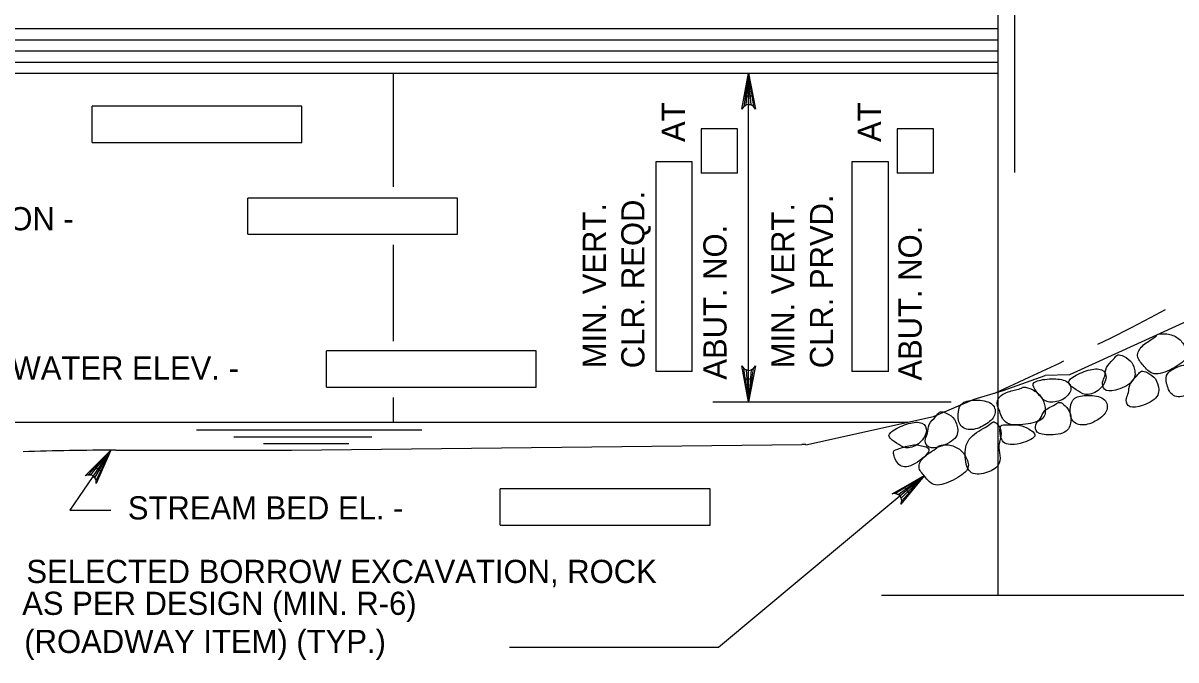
# Model space of a CAD drawing. Extents: x 638263 to 640360, y 293683 to 298655.
# Drawn here: x 638627.4 to 638776.5, y 296792.9 to 296875.4 of the extents above; entities that cross this region are included whole.
import ezdxf

# ---------------------------------------------------------------- set-up
doc = ezdxf.new("R2010")
doc.units = 0
for name, color, linetype in [('3', 7, 'Continuous'), ('4', 7, 'Continuous'), ('5', 7, 'Continuous'), ('8', 7, 'Continuous')]:
    doc.layers.add(name, color=color, linetype=linetype)

msp = doc.modelspace()

# ---------------------------------------------------------------- linework, layer by layer
at = {"layer": '3'}
for p, q in [((638753.51, 296889.11), (638753.51, 296827.61)), ((638574.73, 296868.92), (638753.51, 296868.92)), ((638675.26, 296868.92), (638675.26, 296854.18)), ((638675.26, 296846.69), (638675.26, 296834.19)), ((638794.37, 296844.32), (638762.78, 296829.83)), ((638762.78, 296829.83), (638759.63, 296829.75)), ((638675.26, 296826.9), (638675.26, 296823.72)), ((638753.51, 296827.61), (638753.51, 296801.33)), ((638581.08, 296823.72), (638741.81, 296823.72)), ((638649.8, 296822.71), (638678.95, 296822.71)), ((638654.62, 296821.82), (638672.49, 296821.82)), ((638658.48, 296820.95), (638669.51, 296820.95)), ((638738.44, 296801.33), (638781.13, 296801.33))]:
    msp.add_line(p, q, dxfattribs=at)
msp.add_lwpolyline([(638639.37, 296820.1), (638662.09, 296820.1), (638728.15, 296820.82)], dxfattribs=at)
for centre, radius, start, end in [((638728.15, 296809.34), 11.48, 87.4213, 90), ((638639.37, 296471.99), 348.1, 90, 91.9788)]:
    msp.add_arc(centre, radius, start, end, dxfattribs=at)
for points in [[(638774.05, 296834.95), (638773.99, 296834.86), (638773.66, 296834.58), (638772.07, 296833.66), (638771.28, 296832.23), (638772.28, 296831.18), (638773.49, 296829.55), (638776.06, 296830.55), (638778.28, 296831.96), (638777.74, 296833.56), (638776.95, 296834.68), (638775.34, 296835.29), (638774, 296835.08), (638774.1, 296835.03), (638774.05, 296834.95)], [(638767.33, 296829.69), (638767.27, 296829.39), (638766.96, 296829.03), (638767.11, 296827.8), (638768.46, 296827.63), (638771.35, 296828.88), (638771.26, 296830.64), (638770.75, 296831.74), (638769.49, 296832.45), (638768.83, 296832.48), (638768.53, 296831.86), (638767.36, 296830.83), (638767.4, 296829.99), (638767.33, 296829.69)], [(638775.49, 296830.04), (638775.21, 296829.67), (638775.25, 296828.83), (638775.88, 296827), (638777.72, 296826.87), (638779.47, 296828.49), (638780.17, 296830.12), (638779.2, 296831.46), (638776.93, 296831.06), (638775.77, 296830.41), (638775.49, 296830.04)], [(638762.85, 296828.5), (638763.09, 296828.25), (638763.95, 296827.69), (638765.06, 296827.05), (638767.04, 296827.99), (638767.8, 296829.92), (638766.71, 296830.82), (638764.69, 296830.38), (638762.51, 296829.24), (638762.61, 296828.76), (638762.85, 296828.5)], [(638770.4, 296827.57), (638770.33, 296827.27), (638770.03, 296826.91), (638770.18, 296825.68), (638771.53, 296825.51), (638774.42, 296826.76), (638774.33, 296828.52), (638773.81, 296829.62), (638772.55, 296830.33), (638771.9, 296830.36), (638771.6, 296829.75), (638770.43, 296828.71), (638770.46, 296827.87), (638770.4, 296827.57)], [(638756.63, 296828.18), (638756.55, 296828.12), (638756.15, 296827.96), (638754.35, 296827.61), (638753.13, 296826.51), (638753.74, 296825.19), (638754.35, 296823.26), (638757.11, 296823.37), (638759.67, 296823.98), (638759.67, 296825.67), (638759.29, 296826.99), (638757.97, 296828.09), (638756.63, 296828.33), (638756.71, 296828.24), (638756.63, 296828.18)], [(638758.15, 296828.25), (638758.29, 296827.93), (638758.93, 296827.12), (638759.77, 296826.16), (638761.95, 296826.4), (638763.29, 296827.98), (638762.56, 296829.18), (638760.51, 296829.43), (638758.07, 296829.06), (638758, 296828.57), (638758.15, 296828.25)], [(638748.95, 296826.2), (638748.57, 296825.94), (638748.33, 296825.13), (638748.33, 296823.2), (638750.03, 296822.48), (638752.21, 296823.44), (638753.4, 296824.76), (638752.92, 296826.34), (638750.64, 296826.69), (638749.33, 296826.46), (638748.95, 296826.2)], [(638763.46, 296826.81), (638763.08, 296826.55), (638762.84, 296825.74), (638762.84, 296823.81), (638764.54, 296823.08), (638766.72, 296824.05), (638767.91, 296825.37), (638767.43, 296826.95), (638765.15, 296827.3), (638763.85, 296827.07), (638763.46, 296826.81)], [(638744.4, 296822.32), (638744.33, 296822.02), (638744.03, 296821.66), (638744.18, 296820.43), (638745.52, 296820.26), (638748.42, 296821.51), (638748.32, 296823.27), (638747.81, 296824.37), (638746.55, 296825.08), (638745.9, 296825.11), (638745.6, 296824.49), (638744.42, 296823.46), (638744.46, 296822.62), (638744.4, 296822.32)], [(638759.02, 296824.25), (638758.86, 296823.99), (638758.45, 296823.74), (638758.2, 296822.53), (638759.41, 296821.94), (638762.56, 296822.18), (638763.04, 296823.87), (638762.91, 296825.08), (638761.95, 296826.16), (638761.34, 296826.4), (638760.86, 296825.91), (638759.41, 296825.32), (638759.18, 296824.51), (638759.02, 296824.25)], [(638739.6, 296821.59), (638739.84, 296821.34), (638740.7, 296820.78), (638741.81, 296820.14), (638743.79, 296821.08), (638744.55, 296823.01), (638743.46, 296823.91), (638741.44, 296823.47), (638739.26, 296822.33), (638739.36, 296821.85), (638739.6, 296821.59)], [(638752.9, 296823.75), (638752.74, 296823.71), (638752.48, 296823.31), (638749.59, 296821.87), (638749.11, 296819.69), (638749.59, 296816.79), (638752, 296817.03), (638753.82, 296818), (638753.82, 296819.45), (638753.45, 296820.66), (638754.18, 296822.35), (638753.45, 296823.56), (638753.06, 296823.79), (638752.9, 296823.75)], [(638754.5, 296823.39), (638754.06, 296823.39), (638753.74, 296823.39), (638753.74, 296821.21), (638755.31, 296820.49), (638759.06, 296821.81), (638757.49, 296822.91), (638756.4, 296823.39), (638754.95, 296823.39), (638754.5, 296823.39)], [(638740.54, 296820.23), (638740.12, 296820.08), (638739.81, 296819.98), (638740.52, 296817.92), (638742.24, 296817.75), (638745.36, 296820.22), (638743.52, 296820.74), (638742.33, 296820.85), (638740.96, 296820.37), (638740.54, 296820.23)], [(638745.77, 296820.55), (638745.72, 296820.47), (638745.38, 296820.18), (638743.8, 296819.26), (638743, 296817.83), (638744.01, 296816.78), (638745.21, 296815.15), (638747.79, 296816.16), (638750.01, 296817.57), (638749.46, 296819.17), (638748.67, 296820.29), (638747.07, 296820.9), (638745.72, 296820.69), (638745.83, 296820.64), (638745.77, 296820.55)]]:
    msp.add_open_spline(points, degree=3, dxfattribs=at)
at = {"layer": '4'}
for p, q in [((638755.67, 296924.3), (638755.67, 296856.06)), ((638721.25, 296826.36), (638721.25, 296868.92)), ((638663.44, 296864.64), (638636.3, 296864.64)), ((638636.3, 296859.94), (638636.3, 296864.64)), ((638663.44, 296859.94), (638663.44, 296864.64)), ((638715.1, 296861.71), (638715.1, 296855.96)), ((638719.8, 296861.71), (638715.1, 296861.71)), ((638719.8, 296855.96), (638719.8, 296861.71)), ((638740.47, 296861.71), (638740.47, 296855.96)), ((638745.17, 296861.71), (638740.47, 296861.71)), ((638745.17, 296855.96), (638745.17, 296861.71)), ((638636.3, 296859.94), (638663.44, 296859.94)), ((638709.25, 296857.45), (638709.25, 296830.3)), ((638713.96, 296857.45), (638709.25, 296857.45)), ((638713.96, 296830.3), (638713.96, 296857.45)), ((638734.62, 296857.45), (638734.62, 296830.3)), ((638739.33, 296857.45), (638734.62, 296857.45)), ((638739.33, 296830.3), (638739.33, 296857.45)), ((638719.8, 296855.96), (638715.1, 296855.96)), ((638745.17, 296855.96), (638740.47, 296855.96)), ((638656.42, 296848.05), (638656.42, 296852.75)), ((638683.57, 296852.75), (638656.42, 296852.75)), ((638683.57, 296848.05), (638683.57, 296852.75)), ((638656.42, 296848.05), (638683.57, 296848.05)), ((638666.61, 296828.24), (638666.61, 296832.95)), ((638693.76, 296832.95), (638666.61, 296832.95)), ((638693.76, 296828.24), (638693.76, 296832.95)), ((638713.96, 296830.3), (638709.25, 296830.3)), ((638739.33, 296830.3), (638734.62, 296830.3)), ((638666.61, 296828.24), (638693.76, 296828.24)), ((638716.63, 296826.36), (638747.46, 296826.36)), ((638638.73, 296820.1), (638633.39, 296812.32)), ((638743.97, 296816.77), (638717.33, 296794.54)), ((638716.26, 296815.07), (638689.11, 296815.07)), ((638689.11, 296810.37), (638689.11, 296815.07)), ((638716.26, 296810.37), (638716.26, 296815.07)), ((638633.39, 296812.32), (638638.73, 296812.32)), ((638689.11, 296810.37), (638716.26, 296810.37)), ((638717.33, 296794.54), (638690.32, 296794.54))]:
    msp.add_line(p, q, dxfattribs=at)
for points in [[(638721.25, 296868.92), (638722.13, 296864.26), (638721.88, 296864.62), (638721.57, 296864.81), (638721.25, 296864.86), (638720.94, 296864.81), (638720.63, 296864.62), (638720.38, 296864.26), (638721.25, 296868.92), (638720.63, 296864.62), (638720.94, 296864.81), (638721.25, 296868.92), (638721.25, 296864.86), (638721.57, 296864.81), (638721.25, 296868.92), (638721.88, 296864.62)], [(638721.25, 296826.36), (638720.38, 296831.02), (638720.63, 296830.66), (638720.94, 296830.48), (638721.25, 296830.42), (638721.57, 296830.48), (638721.88, 296830.66), (638722.13, 296831.02), (638721.25, 296826.36), (638721.88, 296830.66), (638721.57, 296830.48), (638721.25, 296826.36), (638721.25, 296830.42), (638720.94, 296830.48), (638721.25, 296826.36), (638720.63, 296830.66)], [(638728.66, 296820.8), (638745.18, 296824.47), (638750.43, 296826.71), (638754.2, 296827.8), (638759.63, 296829.75)], [(638638.73, 296820.1), (638636.81, 296815.76), (638636.81, 296816.2), (638636.66, 296816.53), (638636.43, 296816.75), (638636.14, 296816.88), (638635.78, 296816.91), (638635.37, 296816.75), (638638.73, 296820.1), (638635.78, 296816.91), (638636.14, 296816.88), (638638.73, 296820.1), (638636.43, 296816.75), (638636.66, 296816.53), (638638.73, 296820.1), (638636.81, 296816.2)], [(638743.97, 296816.77), (638740.95, 296813.11), (638741.07, 296813.53), (638741.01, 296813.89), (638740.85, 296814.16), (638740.61, 296814.37), (638740.27, 296814.49), (638739.84, 296814.45), (638743.97, 296816.77), (638740.27, 296814.49), (638740.61, 296814.37), (638743.97, 296816.77), (638740.85, 296814.16), (638741.01, 296813.89), (638743.97, 296816.77), (638741.07, 296813.53)]]:
    msp.add_lwpolyline(points, dxfattribs=at)
for points in [[(638720.76, 296865.97), (638721.75, 296865.97), (638721.25, 296868.92)], [(638720.76, 296829.31), (638721.75, 296829.31), (638721.25, 296826.36)], [(638636.65, 296817.94), (638637.46, 296817.38), (638638.73, 296820.09)], [(638741.39, 296815.25), (638742.02, 296814.5), (638743.97, 296816.77)]]:
    msp.add_lwpolyline(points, close=True, dxfattribs=at)
at = {"layer": '5'}
for p, q in [((638574.73, 296874.69), (638753.51, 296874.69)), ((638574.73, 296873.25), (638753.51, 296873.25)), ((638574.73, 296871.81), (638753.51, 296871.81)), ((638574.73, 296870.36), (638753.51, 296870.36))]:
    msp.add_line(p, q, dxfattribs=at)
at = {"layer": '8'}
for p, q in [((638770.81, 296836), (638773.26, 296837.29)), ((638773.26, 296837.29), (638775.2, 296838.33)), ((638768.06, 296834.6), (638770.81, 296836)), ((638766.46, 296833.81), (638768.06, 296834.6)), ((638757.54, 296829.53), (638761.48, 296831.38)), ((638761.48, 296831.38), (638762.04, 296831.65)), ((638753.11, 296827.49), (638757.54, 296829.53))]:
    msp.add_line(p, q, dxfattribs=at)

# ---------------------------------------------------------------- texts
at = {"layer": '4'}
for s, p in [('AT', (638713.01, 296860)), ('AT', (638738.38, 296860)), ('CLR. REQD.', (638707.77, 296830.7)), ('CLR. PRVD.', (638732.18, 296830.7)), ('MIN. VERT.', (638702.77, 296830.7)), ('MIN. VERT.', (638727.18, 296830.7)), ('ABUT. NO. ', (638718.39, 296829.22)), ('ABUT. NO. ', (638743.64, 296829.1))]:
    msp.add_text(s, height=3, rotation=90, dxfattribs=at).set_placement(p)
for s, p in [('Q        ELEVATION - ', (638596.91, 296848.57)), ('NORMAL WATER ELEV. -', (638607.58, 296829.24)), ('STREAM BED EL. -', (638640.91, 296811.12)), ('SELECTED BORROW EXCAVATION, ROCK', (638627.78, 296802.89)), ('AS PER DESIGN (MIN. R-6)', (638627.24, 296798.76)), ('(ROADWAY ITEM) (TYP.)', (638627.51, 296793.82))]:
    msp.add_text(s, height=3, dxfattribs=at).set_placement(p)

doc.saveas('drawing.dxf')
